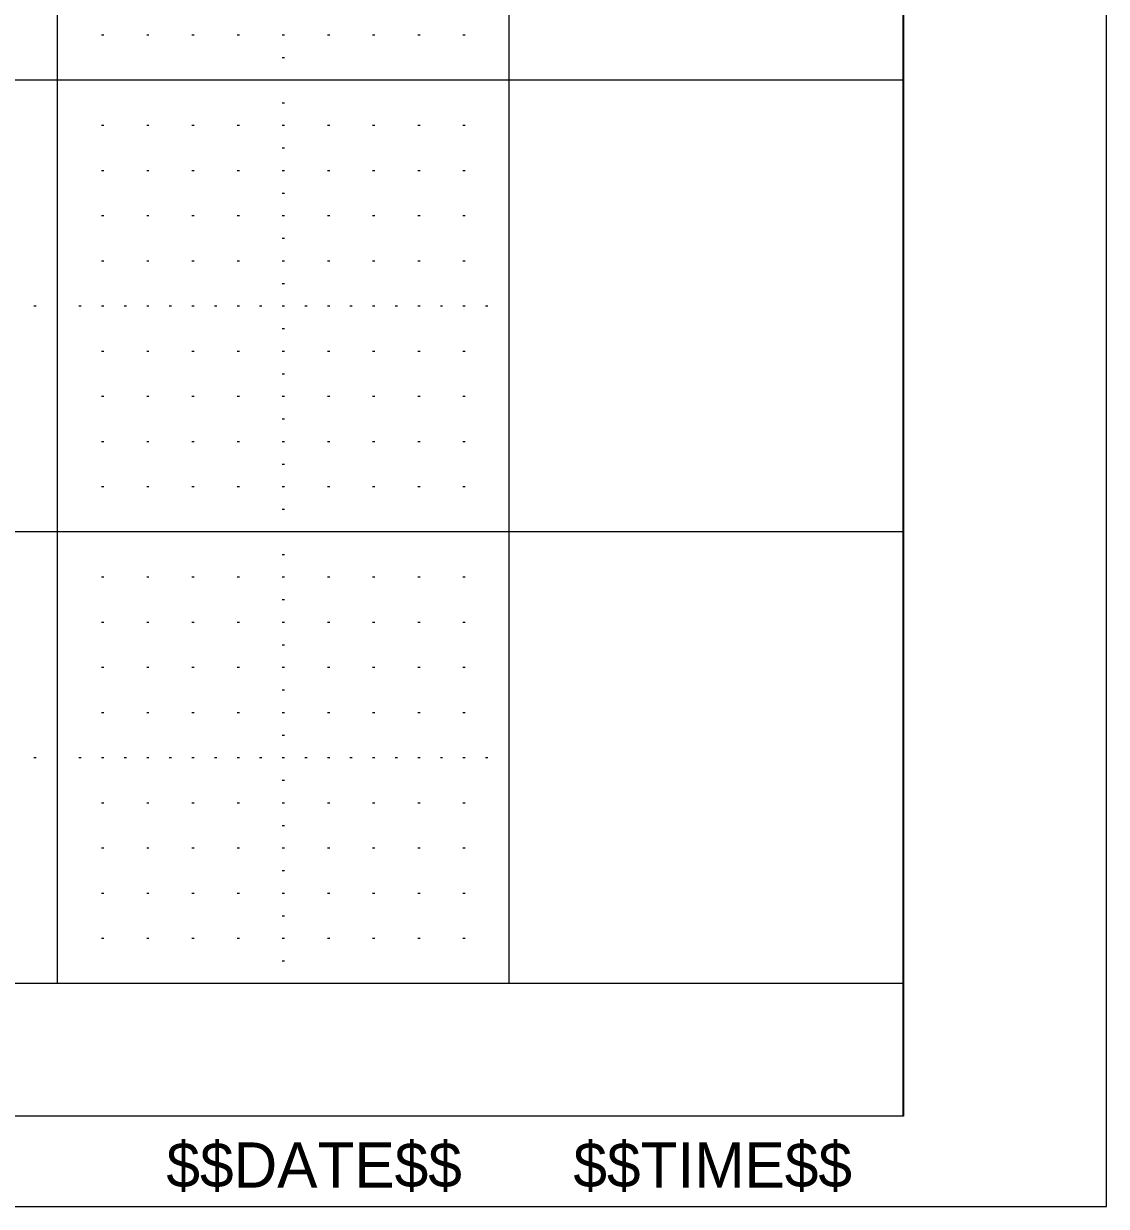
# Model space of a CAD drawing. Extents: x -1.3 to 32.1, y -0.2 to 20.7.
# Drawn here: x 29.67 to 32.067, y -0.2 to 2.418 of the extents above; entities that cross this region are included whole.
import ezdxf

# ---------------------------------------------------------------- set-up
doc = ezdxf.new("R2010")
doc.units = 0
for name, color, linetype in [('Level 1', 7, 'Continuous'), ('Level 37', 7, 'Continuous'), ('Level 48', 7, 'Continuous'), ('Level 5', 7, 'Continuous'), ('Level 6', 7, 'Continuous'), ('Level 62', 7, 'Continuous'), ('Level 63', 7, 'Continuous')]:
    doc.layers.add(name, color=color, linetype=linetype)

msp = doc.modelspace()

# ---------------------------------------------------------------- linework, layer by layer
at = {"layer": 'Level 1'}
for q in [(31.617, 20.545), (-0.001, -0.001)]:
    msp.add_line((31.617, -0.001), q, dxfattribs=at)
at = {"layer": 'Level 37'}
for p, q in [((31.618, 10.272), (31.618, -0.001)), ((31.618, -0.001), (-0.001, -0.001))]:
    msp.add_line(p, q, dxfattribs=at)
at = {"layer": 'Level 5'}
for p, q in [((29.8425, 2.393), (29.8475, 2.393)), ((29.9425, 2.393), (29.9475, 2.393)), ((30.0425, 2.393), (30.0475, 2.393)), ((30.1425, 2.393), (30.1475, 2.393)), ((30.2425, 2.393), (30.2475, 2.393)), ((30.3425, 2.393), (30.3475, 2.393)), ((30.4425, 2.393), (30.4475, 2.393)), ((30.5425, 2.393), (30.5475, 2.393)), ((30.6425, 2.393), (30.6475, 2.393)), ((30.2425, 2.343), (30.2475, 2.343)), ((30.2425, 2.243), (30.2475, 2.243)), ((29.8425, 2.193), (29.8475, 2.193)), ((29.9425, 2.193), (29.9475, 2.193)), ((30.0425, 2.193), (30.0475, 2.193)), ((30.1425, 2.193), (30.1475, 2.193)), ((30.2425, 2.193), (30.2475, 2.193)), ((30.3425, 2.193), (30.3475, 2.193)), ((30.4425, 2.193), (30.4475, 2.193)), ((30.5425, 2.193), (30.5475, 2.193)), ((30.6425, 2.193), (30.6475, 2.193)), ((30.2425, 2.143), (30.2475, 2.143)), ((29.8425, 2.093), (29.8475, 2.093)), ((29.9425, 2.093), (29.9475, 2.093)), ((30.0425, 2.093), (30.0475, 2.093)), ((30.1425, 2.093), (30.1475, 2.093)), ((30.2425, 2.093), (30.2475, 2.093)), ((30.3425, 2.093), (30.3475, 2.093)), ((30.4425, 2.093), (30.4475, 2.093)), ((30.5425, 2.093), (30.5475, 2.093)), ((30.6425, 2.093), (30.6475, 2.093)), ((30.2425, 2.043), (30.2475, 2.043)), ((29.8425, 1.993), (29.8475, 1.993)), ((29.9425, 1.993), (29.9475, 1.993)), ((30.0425, 1.993), (30.0475, 1.993)), ((30.1425, 1.993), (30.1475, 1.993)), ((30.2425, 1.993), (30.2475, 1.993)), ((30.3425, 1.993), (30.3475, 1.993)), ((30.4425, 1.993), (30.4475, 1.993)), ((30.5425, 1.993), (30.5475, 1.993)), ((30.6425, 1.993), (30.6475, 1.993)), ((30.2425, 1.943), (30.2475, 1.943)), ((29.8425, 1.893), (29.8475, 1.893)), ((29.9425, 1.893), (29.9475, 1.893)), ((30.0425, 1.893), (30.0475, 1.893)), ((30.1425, 1.893), (30.1475, 1.893)), ((30.2425, 1.893), (30.2475, 1.893)), ((30.3425, 1.893), (30.3475, 1.893)), ((30.4425, 1.893), (30.4475, 1.893)), ((30.5425, 1.893), (30.5475, 1.893)), ((30.6425, 1.893), (30.6475, 1.893)), ((30.2425, 1.843), (30.2475, 1.843)), ((29.6925, 1.793), (29.6975, 1.793)), ((29.7925, 1.793), (29.7975, 1.793)), ((29.8425, 1.793), (29.8475, 1.793)), ((29.8925, 1.793), (29.8975, 1.793)), ((29.9425, 1.793), (29.9475, 1.793)), ((29.9925, 1.793), (29.9975, 1.793)), ((30.0425, 1.793), (30.0475, 1.793)), ((30.0925, 1.793), (30.0975, 1.793)), ((30.1425, 1.793), (30.1475, 1.793)), ((30.1925, 1.793), (30.1975, 1.793)), ((30.2425, 1.793), (30.2475, 1.793)), ((30.2925, 1.793), (30.2975, 1.793)), ((30.3425, 1.793), (30.3475, 1.793)), ((30.3925, 1.793), (30.3975, 1.793)), ((30.4425, 1.793), (30.4475, 1.793)), ((30.4925, 1.793), (30.4975, 1.793)), ((30.5425, 1.793), (30.5475, 1.793)), ((30.5925, 1.793), (30.5975, 1.793)), ((30.6425, 1.793), (30.6475, 1.793)), ((30.6925, 1.793), (30.6975, 1.793)), ((30.2425, 1.743), (30.2475, 1.743)), ((29.8425, 1.693), (29.8475, 1.693)), ((29.9425, 1.693), (29.9475, 1.693)), ((30.0425, 1.693), (30.0475, 1.693)), ((30.1425, 1.693), (30.1475, 1.693)), ((30.2425, 1.693), (30.2475, 1.693)), ((30.3425, 1.693), (30.3475, 1.693)), ((30.4425, 1.693), (30.4475, 1.693)), ((30.5425, 1.693), (30.5475, 1.693)), ((30.6425, 1.693), (30.6475, 1.693)), ((30.2425, 1.643), (30.2475, 1.643)), ((29.8425, 1.593), (29.8475, 1.593)), ((29.9425, 1.593), (29.9475, 1.593)), ((30.0425, 1.593), (30.0475, 1.593)), ((30.1425, 1.593), (30.1475, 1.593)), ((30.2425, 1.593), (30.2475, 1.593)), ((30.3425, 1.593), (30.3475, 1.593)), ((30.4425, 1.593), (30.4475, 1.593)), ((30.5425, 1.593), (30.5475, 1.593)), ((30.6425, 1.593), (30.6475, 1.593)), ((30.2425, 1.543), (30.2475, 1.543)), ((29.8425, 1.493), (29.8475, 1.493)), ((29.9425, 1.493), (29.9475, 1.493)), ((30.0425, 1.493), (30.0475, 1.493)), ((30.1425, 1.493), (30.1475, 1.493)), ((30.2425, 1.493), (30.2475, 1.493)), ((30.3425, 1.493), (30.3475, 1.493)), ((30.4425, 1.493), (30.4475, 1.493)), ((30.5425, 1.493), (30.5475, 1.493)), ((30.6425, 1.493), (30.6475, 1.493)), ((30.2425, 1.443), (30.2475, 1.443)), ((29.8425, 1.393), (29.8475, 1.393)), ((29.9425, 1.393), (29.9475, 1.393)), ((30.0425, 1.393), (30.0475, 1.393)), ((30.1425, 1.393), (30.1475, 1.393)), ((30.2425, 1.393), (30.2475, 1.393)), ((30.3425, 1.393), (30.3475, 1.393)), ((30.4425, 1.393), (30.4475, 1.393)), ((30.5425, 1.393), (30.5475, 1.393)), ((30.6425, 1.393), (30.6475, 1.393)), ((30.2425, 1.343), (30.2475, 1.343)), ((30.2425, 1.243), (30.2475, 1.243)), ((29.8425, 1.193), (29.8475, 1.193)), ((29.9425, 1.193), (29.9475, 1.193)), ((30.0425, 1.193), (30.0475, 1.193)), ((30.1425, 1.193), (30.1475, 1.193)), ((30.2425, 1.193), (30.2475, 1.193)), ((30.3425, 1.193), (30.3475, 1.193)), ((30.4425, 1.193), (30.4475, 1.193)), ((30.5425, 1.193), (30.5475, 1.193)), ((30.6425, 1.193), (30.6475, 1.193)), ((30.2425, 1.143), (30.2475, 1.143)), ((29.8425, 1.093), (29.8475, 1.093)), ((29.9425, 1.093), (29.9475, 1.093)), ((30.0425, 1.093), (30.0475, 1.093)), ((30.1425, 1.093), (30.1475, 1.093)), ((30.2425, 1.093), (30.2475, 1.093)), ((30.3425, 1.093), (30.3475, 1.093)), ((30.4425, 1.093), (30.4475, 1.093)), ((30.5425, 1.093), (30.5475, 1.093)), ((30.6425, 1.093), (30.6475, 1.093)), ((30.2425, 1.043), (30.2475, 1.043)), ((29.8425, 0.993), (29.8475, 0.993)), ((29.9425, 0.993), (29.9475, 0.993)), ((30.0425, 0.993), (30.0475, 0.993)), ((30.1425, 0.993), (30.1475, 0.993)), ((30.2425, 0.993), (30.2475, 0.993)), ((30.3425, 0.993), (30.3475, 0.993)), ((30.4425, 0.993), (30.4475, 0.993)), ((30.5425, 0.993), (30.5475, 0.993)), ((30.6425, 0.993), (30.6475, 0.993)), ((30.2425, 0.943), (30.2475, 0.943)), ((29.8425, 0.893), (29.8475, 0.893)), ((29.9425, 0.893), (29.9475, 0.893)), ((30.0425, 0.893), (30.0475, 0.893)), ((30.1425, 0.893), (30.1475, 0.893)), ((30.2425, 0.893), (30.2475, 0.893)), ((30.3425, 0.893), (30.3475, 0.893)), ((30.4425, 0.893), (30.4475, 0.893)), ((30.5425, 0.893), (30.5475, 0.893)), ((30.6425, 0.893), (30.6475, 0.893)), ((30.2425, 0.843), (30.2475, 0.843)), ((29.6925, 0.793), (29.6975, 0.793)), ((29.7925, 0.793), (29.7975, 0.793)), ((29.8425, 0.793), (29.8475, 0.793)), ((29.8925, 0.793), (29.8975, 0.793)), ((29.9425, 0.793), (29.9475, 0.793)), ((29.9925, 0.793), (29.9975, 0.793)), ((30.0425, 0.793), (30.0475, 0.793)), ((30.0925, 0.793), (30.0975, 0.793)), ((30.1425, 0.793), (30.1475, 0.793)), ((30.1925, 0.793), (30.1975, 0.793)), ((30.2425, 0.793), (30.2475, 0.793)), ((30.2925, 0.793), (30.2975, 0.793)), ((30.3425, 0.793), (30.3475, 0.793)), ((30.3925, 0.793), (30.3975, 0.793)), ((30.4425, 0.793), (30.4475, 0.793)), ((30.4925, 0.793), (30.4975, 0.793)), ((30.5425, 0.793), (30.5475, 0.793)), ((30.5925, 0.793), (30.5975, 0.793)), ((30.6425, 0.793), (30.6475, 0.793)), ((30.6925, 0.793), (30.6975, 0.793)), ((30.2425, 0.743), (30.2475, 0.743)), ((29.8425, 0.693), (29.8475, 0.693)), ((29.9425, 0.693), (29.9475, 0.693)), ((30.0425, 0.693), (30.0475, 0.693)), ((30.1425, 0.693), (30.1475, 0.693)), ((30.2425, 0.693), (30.2475, 0.693)), ((30.3425, 0.693), (30.3475, 0.693)), ((30.4425, 0.693), (30.4475, 0.693)), ((30.5425, 0.693), (30.5475, 0.693)), ((30.6425, 0.693), (30.6475, 0.693)), ((30.2425, 0.643), (30.2475, 0.643)), ((29.8425, 0.593), (29.8475, 0.593)), ((29.9425, 0.593), (29.9475, 0.593)), ((30.0425, 0.593), (30.0475, 0.593)), ((30.1425, 0.593), (30.1475, 0.593)), ((30.2425, 0.593), (30.2475, 0.593)), ((30.3425, 0.593), (30.3475, 0.593)), ((30.4425, 0.593), (30.4475, 0.593)), ((30.5425, 0.593), (30.5475, 0.593)), ((30.6425, 0.593), (30.6475, 0.593)), ((30.2425, 0.543), (30.2475, 0.543)), ((29.8425, 0.493), (29.8475, 0.493)), ((29.9425, 0.493), (29.9475, 0.493)), ((30.0425, 0.493), (30.0475, 0.493)), ((30.1425, 0.493), (30.1475, 0.493)), ((30.2425, 0.493), (30.2475, 0.493)), ((30.3425, 0.493), (30.3475, 0.493)), ((30.4425, 0.493), (30.4475, 0.493)), ((30.5425, 0.493), (30.5475, 0.493)), ((30.6425, 0.493), (30.6475, 0.493)), ((30.2425, 0.443), (30.2475, 0.443)), ((29.8425, 0.393), (29.8475, 0.393)), ((29.9425, 0.393), (29.9475, 0.393)), ((30.0425, 0.393), (30.0475, 0.393)), ((30.1425, 0.393), (30.1475, 0.393)), ((30.2425, 0.393), (30.2475, 0.393)), ((30.3425, 0.393), (30.3475, 0.393)), ((30.4425, 0.393), (30.4475, 0.393)), ((30.5425, 0.393), (30.5475, 0.393)), ((30.6425, 0.393), (30.6475, 0.393)), ((30.2425, 0.343), (30.2475, 0.343))]:
    msp.add_line(p, q, dxfattribs=at)
at = {"layer": 'Level 6'}
for p, q in [((29.745, 0.293), (29.745, 10.293)), ((30.745, 0.293), (30.745, 10.293)), ((31.617, 2.293), (-0.001, 2.293)), ((31.617, 1.293), (-0.001, 1.293)), ((31.617, 0.293), (-0.001, 0.293))]:
    msp.add_line(p, q, dxfattribs=at)
at = {"layer": 'Level 62'}
for p, q in [((31.618, 0), (31.618, 10.294)), ((-0.001, 0), (31.618, 0))]:
    msp.add_line(p, q, dxfattribs=at)
at = {"layer": 'Level 63'}
msp.add_lwpolyline([(-1.263, -0.2005), (32.067, -0.2005), (32.067, 20.7465), (-1.263, 20.7465)], close=True, dxfattribs=at)

# ---------------------------------------------------------------- texts
at = {"layer": 'Level 48'}
for s, p in [('$$DATE$$', (29.986, -0.159)), ('$$TIME$$', (30.887, -0.159))]:
    msp.add_text(s, height=0.1, dxfattribs=at).set_placement(p)

doc.saveas('drawing.dxf')
